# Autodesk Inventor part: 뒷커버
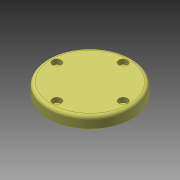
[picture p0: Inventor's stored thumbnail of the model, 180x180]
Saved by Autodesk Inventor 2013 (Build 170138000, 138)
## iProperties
Created: 2010-03
Part Number: 뒷커버
Document SubType Name: Modeling
Designer: 진현석
Density: 1 g/cm^3
Material: 알루미늄 6061
Author: 진현석
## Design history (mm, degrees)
sketch "스케치1"
  geometry: C1 r 38 at (0, 0); 1 further point
  constraints: 1 centre point, 1 coincident
  dimensions: "d46" = 76 diameter of C1
extrude "돌출1" new body sketch "스케치1" distance "d0" = 10; taper "d1" = 0 deg
sketch "스케치2"
  geometry: C1 r 26 at (0, 0); C2 r 38 at (0, 0) reference
  constraints: 1 centre point, 1 concentric
  dimensions: "d47" = 52 diameter of C1
extrude "돌출3" join sketch "스케치2" distance "d4" = 3; taper "d5" = 0 deg
sketch "스케치4"
  geometry: C1 r 23 at (0, 0); C2 r 26 at (0, 0) reference
  constraints: 1 centre point, 1 concentric
  dimensions: "d40" = 3 radial gap between concentric circles of C2 C1
extrude "돌출5" cut sketch "스케치4" distance "d23" = 6; taper "d24" = 0 deg
fillet "모깎기1" dims "d25" = 3
sketch "스케치5" dims "d41" = 60
  geometry: C1 r 38 at (0, 0) reference; 2 further points
  constraints: 2 vertical alignment, 3 other
hole "구멍2" sketch "스케치5" at (0, 30) diameter "d27" = 4.5; stored, may be unused: countersink angle "d31" = 90 deg, drill point angle "d33" = 118 deg; dims "d28" = 6, "d29" = 8, "d30" = 4.4, "d32" = 8
fillet "모깎기2" dims "d37" = 3
chamfer "모따기1" distance "d43" = 1; stored, may be unused: second distance "d44" = 2, angle "d45" = 45 deg
node "솔리드1"
pattern_circular "원형 패턴2" dims angle "d35" = 360 deg
